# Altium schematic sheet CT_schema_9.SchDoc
size 254 x 194 mm
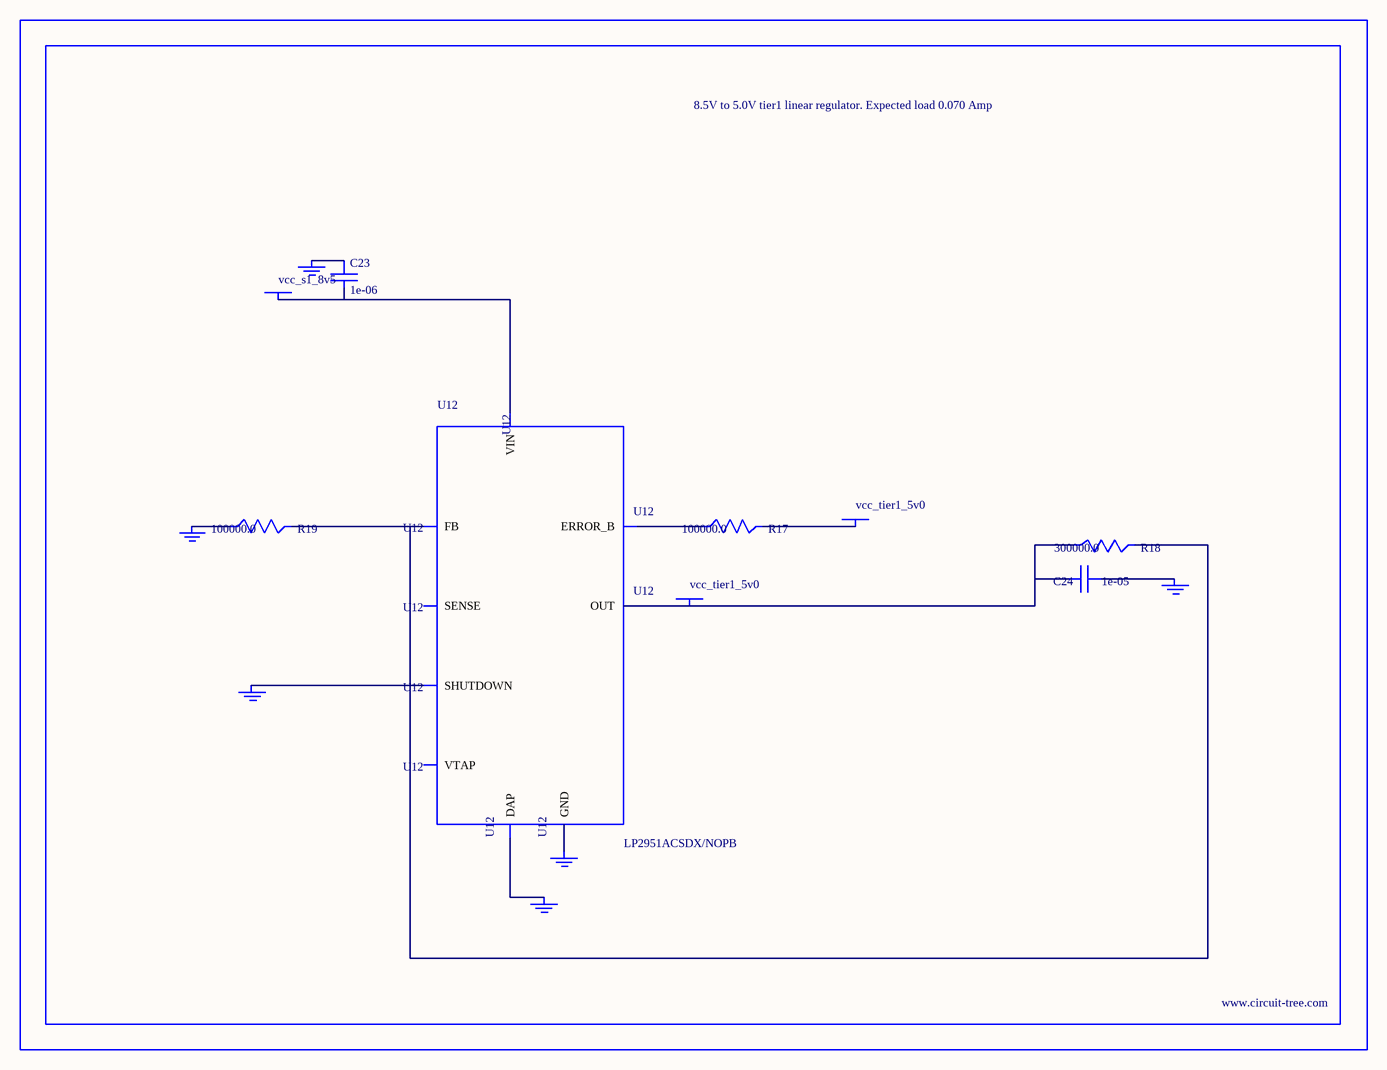
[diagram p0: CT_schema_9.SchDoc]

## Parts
BORDER8  (no value)
C23  1e-06  [C0603]
C24  1e-05  [C1210]
GND_INSTANCE_8_0  (no value)
GND_INSTANCE_8_1  (no value)
GND_INSTANCE_8_2  (no value)
GND_INSTANCE_8_3  (no value)
GND_INSTANCE_8_4  (no value)
GND_INSTANCE_8_5  (no value)
POWER_INSTANCE_8_0  vcc_tier1_5v0
POWER_INSTANCE_8_1  vcc_s1_8v5
POWER_INSTANCE_8_2  vcc_tier1_5v0
R17  100000.0  [R0603]
R18  300000.0  [R0603]
R19  100000.0  [R0603]
U12  LP2951ACSDX/NOPB  [WSON-8]

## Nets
NetC23_1: C23.1 GND_INSTANCE_8_3.0(GND)
NetC23_2: C23.2 POWER_INSTANCE_8_1.0(PWR) U12.8(VIN)
NetC24_1: C24.1 GND_INSTANCE_8_0.0(GND)
NetC24_2: C24.2 POWER_INSTANCE_8_2.0(PWR) R18.1 U12.1(OUT)
NetGND_INSTANCE_8_1_0: GND_INSTANCE_8_1.0(GND) U12.3(SHUTDOWN)
NetGND_INSTANCE_8_2_0: GND_INSTANCE_8_2.0(GND) R19.1
NetGND_INSTANCE_8_4_0: GND_INSTANCE_8_4.0(GND) U12.PAD(DAP)
NetGND_INSTANCE_8_5_0: GND_INSTANCE_8_5.0(GND) U12.4(GND)
NetPOWER_INSTANCE_8_0_0: POWER_INSTANCE_8_0.0(PWR) R17.2
NetR17_1: R17.1 U12.5(ERROR_B)
NetR18_2: R18.2 R19.2 U12.7(FB)

Not connected (* = marked no-connect by the designer): U12 2(SENSE) 6(VTAP)

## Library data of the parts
BORDER8 = BORDER_PAGE8
C23 = C0603C105K3RACTU
C24 = GRM32DR61E106MA12L
GND_INSTANCE_8_0-GND_INSTANCE_8_5 = GND
POWER_INSTANCE_8_0-POWER_INSTANCE_8_2 = PWR
R17 R19 = RC0603JR-07100KL
R18 = RC0603JR-07300KL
